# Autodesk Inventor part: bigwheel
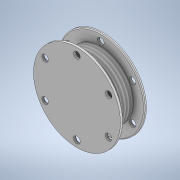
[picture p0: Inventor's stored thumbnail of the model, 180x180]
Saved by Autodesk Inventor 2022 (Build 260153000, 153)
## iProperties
Created: 2021-07
Part Number: bigwheel
Material: Generic
Document SubType Name: Modeling
Designer: Astami
Density: 1 g/cm^3
Appearance: Default
Author: Astami
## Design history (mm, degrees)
sketch "Sketch1"
  geometry: C1 r 100 at (0, 0); 1 further point
  constraints: 1 centre point, 1 coincident
  dimensions: "d0" = 200 diameter of C1
extrude "Extrusion1" new body sketch "Sketch1" distance "d1" = 5; taper "d2" = 0 deg
sketch "Sketch2"
  geometry: C1 r 75 at (0, 0); 1 further point
  constraints: 1 centre point, 1 coincident
  dimensions: "d3" = 150 diameter of C1
extrude "Extrusion2" join sketch "Sketch2" distance "d4" = 50; taper "d5" = 0 deg
sketch "Sketch3"
  geometry: C1 r 100 at (0, 0); 1 further point
  constraints: 1 centre point, 1 coincident
  dimensions: "d6" = 200 diameter of C1
extrude "Extrusion3" join sketch "Sketch3" distance "d7" = 5; taper "d8" = 0 deg
thread "Thread1" dims "d9" = 49.433, "d10" = 0
fillet "Fillet1" dims "d11" = 2
chamfer "Chamfer1" distance "d12" = 2; stored, may be unused: second distance "d13" = 2, angle "d14" = 45 deg
sketch "Sketch4"
  geometry: C1 r 10 at (0, 0); 1 further point
  constraints: 1 centre point, 1 coincident
  dimensions: "d15" = 20 diameter of C1
extrude "Extrusion4" cut sketch "Sketch4" extent not by distance; stored distance "d16" = 0; taper "d17" = 0 deg
sketch "Sketch5"
  geometry: C1 r 7.5 at (0, 84.48); 1 further point
  constraints: 1 centre point
  dimensions: "d18" = 15 diameter of C1
extrude "Extrusion5" cut sketch "Sketch5" extent not by distance; stored distance "d19" = 0; taper "d20" = 0 deg
pattern_circular "Circular Pattern1" dims angle "d22" = 360 deg
sketch "Sketch6"
  geometry: C1 r 7.5 at (0, 84.522); 1 further point
  constraints: 1 centre point
  dimensions: "d24" = 15 diameter of C1
extrude "Extrusion6" cut sketch "Sketch6" extent not by distance; stored distance "d25" = 0; taper "d26" = 0 deg
body "Solid1"
